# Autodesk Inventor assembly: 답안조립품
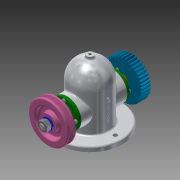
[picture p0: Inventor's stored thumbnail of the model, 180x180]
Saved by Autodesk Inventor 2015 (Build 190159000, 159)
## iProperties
Created: 2019-11
Part Number: 답안조립품
Document SubType Name: Assembly
Designer: now
Author: now
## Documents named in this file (14)
- C:\Users\now\Desktop\지용\491104V1037\491104V1037\답안조립품.iam
- C:\Users\now\Desktop\지용\491104V1037\491104V1037\V-벨트풀리.ipt
- V-벨트풀리.ipt
- C:\Users\now\Desktop\지용\491104V1037\491104V1037\너트 M12x1.25.ipt
- C:\Users\now\Desktop\지용\491104V1037\491104V1037\베어링 6203.ipt
- C:\Users\now\Desktop\지용\491104V1037\491104V1037\본체.ipt
- C:\Users\now\Desktop\지용\491104V1037\491104V1037\볼트 M4.ipt
- C:\Users\now\Desktop\지용\491104V1037\491104V1037\부시.ipt
- C:\Users\now\Desktop\지용\491104V1037\491104V1037\스퍼기어.ipt
- C:\Users\now\Desktop\지용\491104V1037\491104V1037\오일 실 26 38 8.ipt
- C:\Users\now\Desktop\지용\491104V1037\491104V1037\와셔 12x24.ipt
- C:\Users\now\Desktop\지용\491104V1037\491104V1037\축.ipt
- C:\Users\now\Desktop\지용\491104V1037\491104V1037\커버.ipt
- C:\Users\now\Desktop\지용\491104V1037\491104V1037\키 5x5x12.ipt
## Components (1 placed, 1 different names)
1. V-벨트풀리:1 — 각도:4
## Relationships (1: Angle 1)
- 각도:4 [Angle]: V-벨트풀리:1
